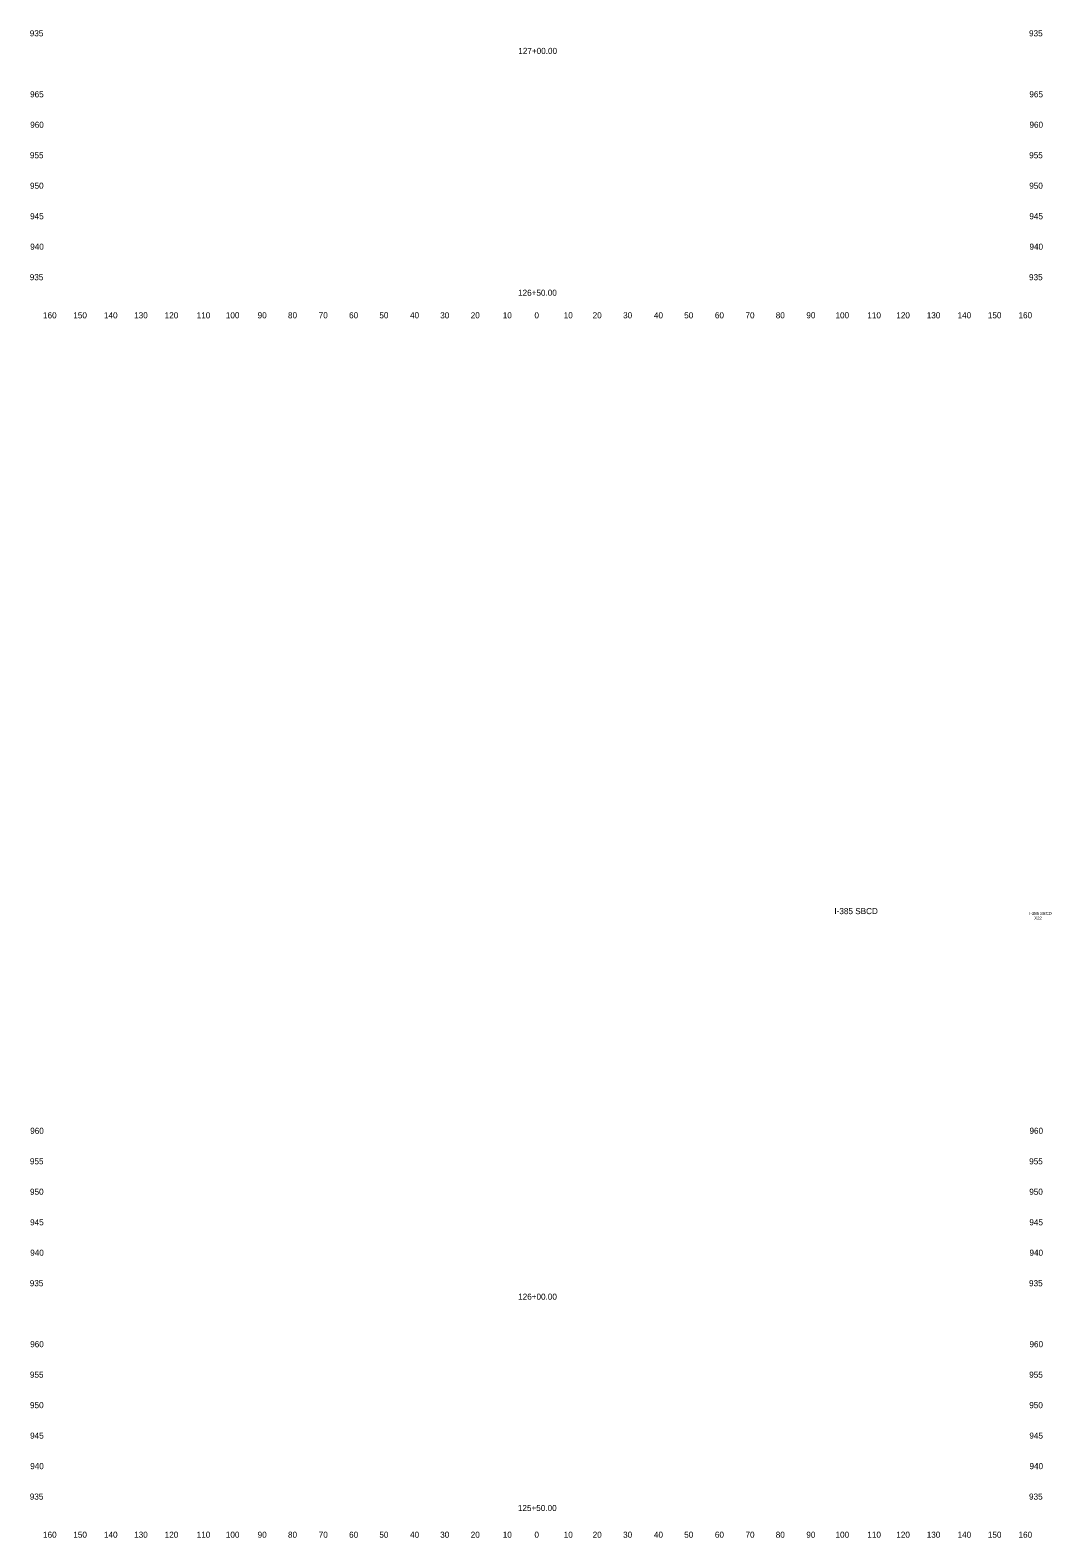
# Model space of a CAD drawing. Extents: x 4994 to 6876, y 4997 to 8804.
# Drawn here: x 6023.9 to 6358.7, y 5397.5 to 5892 of the extents above; entities that cross this region are included whole.
import ezdxf

# ---------------------------------------------------------------- set-up
doc = ezdxf.new("R2010")
doc.units = 0
for name, color, linetype in [('RD_SHT_ID', 7, 'Continuous'), ('RD_XS_TX_Offset', 7, 'Continuous'), ('RD_XS_TX_Station', 7, 'Continuous')]:
    doc.layers.add(name, color=color, linetype=linetype)

msp = doc.modelspace()

# ---------------------------------------------------------------- texts
at = {"layer": 'RD_SHT_ID'}
for s, height, p in [('I-385 SBCD', 2, (6287.69, 5602.06)), ('I-385 SBCD', 1, (6351.63, 5601.8)), ('X22', 1, (6353.29, 5600.3))]:
    msp.add_text(s, height=height, dxfattribs=at).set_placement(p)
at = {"layer": 'RD_XS_TX_Offset'}
for s, p in [('935', (6023.75, 5890)), ('935', (6351.55, 5890)), ('965', (6023.86, 5870)), ('965', (6351.66, 5870)), ('960', (6023.89, 5860)), ('960', (6351.69, 5860)), ('955', (6023.8, 5850)), ('955', (6351.6, 5850)), ('950', (6023.83, 5840)), ('950', (6351.63, 5840)), ('945', (6023.86, 5830)), ('945', (6351.66, 5830)), ('940', (6023.89, 5820)), ('940', (6351.69, 5820)), ('935', (6023.75, 5810)), ('935', (6351.55, 5810)), ('160', (6028.1, 5797.5)), ('150', (6038.04, 5797.5)), ('140', (6048.1, 5797.5)), ('130', (6057.99, 5797.5)), ('120', (6068.01, 5797.5)), ('110', (6078.51, 5797.5)), ('100', (6088.07, 5797.5)), ('90', (6098.5, 5797.5)), ('80', (6108.46, 5797.5)), ('70', (6118.54, 5797.5)), ('60', (6128.5, 5797.5)), ('50', (6138.43, 5797.5)), ('40', (6148.5, 5797.5)), ('30', (6158.39, 5797.5)), ('20', (6168.4, 5797.5)), ('10', (6178.91, 5797.5)), ('0', (6189.3, 5797.5)), ('0', (6189.3, 5797.5)), ('10', (6198.91, 5797.5)), ('20', (6208.4, 5797.5)), ('30', (6218.39, 5797.5)), ('40', (6228.5, 5797.5)), ('50', (6238.43, 5797.5)), ('60', (6248.5, 5797.5)), ('70', (6258.54, 5797.5)), ('80', (6268.46, 5797.5)), ('90', (6278.5, 5797.5)), ('100', (6288.07, 5797.5)), ('110', (6298.51, 5797.5)), ('120', (6308.01, 5797.5)), ('130', (6317.99, 5797.5)), ('140', (6328.1, 5797.5)), ('150', (6338.04, 5797.5)), ('160', (6348.1, 5797.5)), ('960', (6023.89, 5530)), ('960', (6351.69, 5530)), ('955', (6023.8, 5520)), ('955', (6351.6, 5520)), ('950', (6023.83, 5510)), ('950', (6351.63, 5510)), ('945', (6023.86, 5500)), ('945', (6351.66, 5500)), ('940', (6023.89, 5490)), ('940', (6351.69, 5490)), ('935', (6023.75, 5480)), ('935', (6351.55, 5480)), ('960', (6023.89, 5460)), ('960', (6351.69, 5460)), ('955', (6023.8, 5450)), ('955', (6351.6, 5450)), ('950', (6023.83, 5440)), ('950', (6351.63, 5440)), ('945', (6023.86, 5430)), ('945', (6351.66, 5430)), ('940', (6023.89, 5420)), ('940', (6351.69, 5420)), ('935', (6023.75, 5410)), ('935', (6351.55, 5410)), ('160', (6028.1, 5397.5)), ('150', (6038.04, 5397.5)), ('140', (6048.1, 5397.5)), ('130', (6057.99, 5397.5)), ('120', (6068.01, 5397.5)), ('110', (6078.51, 5397.5)), ('100', (6088.07, 5397.5)), ('90', (6098.5, 5397.5)), ('80', (6108.46, 5397.5)), ('70', (6118.54, 5397.5)), ('60', (6128.5, 5397.5)), ('50', (6138.43, 5397.5)), ('40', (6148.5, 5397.5)), ('30', (6158.39, 5397.5)), ('20', (6168.4, 5397.5)), ('10', (6178.91, 5397.5)), ('0', (6189.3, 5397.5)), ('0', (6189.3, 5397.5)), ('10', (6198.91, 5397.5)), ('20', (6208.4, 5397.5)), ('30', (6218.39, 5397.5)), ('40', (6228.5, 5397.5)), ('50', (6238.43, 5397.5)), ('60', (6248.5, 5397.5)), ('70', (6258.54, 5397.5)), ('80', (6268.46, 5397.5)), ('90', (6278.5, 5397.5)), ('100', (6288.07, 5397.5)), ('110', (6298.51, 5397.5)), ('120', (6308.01, 5397.5)), ('130', (6317.99, 5397.5)), ('140', (6328.1, 5397.5)), ('150', (6338.04, 5397.5)), ('160', (6348.1, 5397.5))]:
    msp.add_text(s, height=2, dxfattribs=at).set_placement(p)
at = {"layer": 'RD_XS_TX_Station'}
for s, p in [('127+00.00', (6184.01, 5884.22)), ('126+50.00', (6183.93, 5804.9)), ('126+00.00', (6183.96, 5475.58)), ('125+50.00', (6183.87, 5406.26))]:
    msp.add_text(s, height=2, dxfattribs=at).set_placement(p)

doc.saveas('drawing.dxf')
